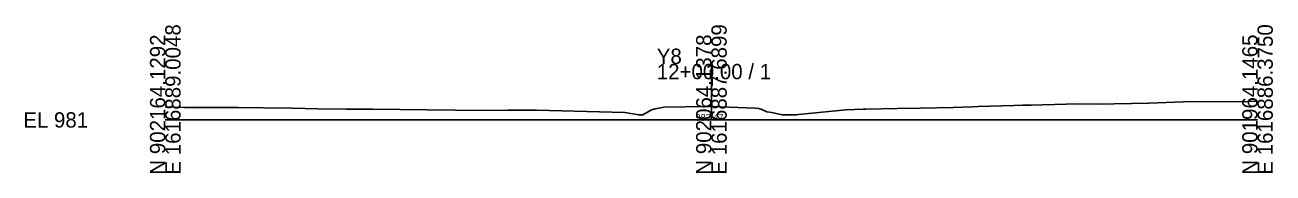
# Model space of a CAD drawing. Extents: x -26 to 1403, y -10 to 3025.
# Drawn here: x -25.7 to 202.8, y 1990.3 to 2017.3 of the extents above; entities that cross this region are included whole.
import ezdxf

# ---------------------------------------------------------------- set-up
doc = ezdxf.new("R2010")
doc.units = 0
for name, color, linetype in [('Exist Cross Section Cell', 7, 'Continuous'), ('Exist XS Center Line Elevation Label', 7, 'Continuous'), ('Exist XS Ground Line', 7, 'Continuous')]:
    doc.layers.add(name, color=color, linetype=linetype)

msp = doc.modelspace()

# ---------------------------------------------------------------- linework, layer by layer
at = {"layer": 'Exist Cross Section Cell'}
for p, q in [((100, 2000), (100, 2010.23)), ((0, 2000), (100, 2000)), ((100, 2000), (200, 2000))]:
    msp.add_line(p, q, dxfattribs=at)
at = {"layer": 'Exist XS Ground Line'}
for p, q in [((0, 2002.38), (3.5, 2002.27)), ((3.5, 2002.27), (7.96, 2002.29)), ((7.96, 2002.29), (13.37, 2002.28)), ((13.37, 2002.28), (17.96, 2002.18)), ((17.96, 2002.18), (23.24, 2002.13)), ((23.24, 2002.13), (27.96, 2002.04)), ((27.96, 2002.04), (33.11, 2001.98)), ((33.11, 2001.98), (37.96, 2001.95)), ((37.96, 2001.95), (42.98, 2001.9)), ((89.04, 2001.87), (89.68, 2002)), ((89.68, 2002), (91.27, 2002.36)), ((91.27, 2002.36), (99.16, 2002.46)), ((99.16, 2002.46), (100.09, 2002.47)), ((100.09, 2002.47), (108.04, 2002.14)), ((108.04, 2002.14), (108.7, 2002.11)), ((108.7, 2002.11), (109.26, 2001.88)), ((127.76, 2001.94), (128.25, 2001.95)), ((128.25, 2001.95), (134.06, 2002.08)), ((134.06, 2002.08), (138.21, 2002.17)), ((138.21, 2002.17), (144.24, 2002.27)), ((144.24, 2002.27), (147.8, 2002.4)), ((147.8, 2002.4), (148.85, 2002.48)), ((148.85, 2002.48), (155.35, 2002.64)), ((155.35, 2002.64), (156.98, 2002.68)), ((156.98, 2002.68), (158.56, 2002.7)), ((158.56, 2002.7), (160.61, 2002.76)), ((160.61, 2002.76), (167.16, 2002.91)), ((167.16, 2002.91), (170.51, 2002.9)), ((170.51, 2002.9), (176.94, 2003.03)), ((176.94, 2003.03), (180.07, 2003.08)), ((180.07, 2003.08), (186.39, 2003.3)), ((186.39, 2003.3), (188.21, 2003.34)), ((188.21, 2003.34), (194.45, 2003.31)), ((194.45, 2003.31), (198.21, 2003.38)), ((198.21, 2003.38), (200, 2003.41)), ((42.98, 2001.9), (47.96, 2001.85)), ((47.96, 2001.85), (53.08, 2001.77)), ((53.08, 2001.77), (57.97, 2001.71)), ((57.97, 2001.71), (62.72, 2001.76)), ((62.72, 2001.76), (67.97, 2001.76)), ((67.97, 2001.76), (81.85, 2001.41)), ((81.85, 2001.41), (84.16, 2001.35)), ((84.16, 2001.35), (86.69, 2000.92)), ((86.69, 2000.92), (87.44, 2000.92)), ((87.44, 2000.92), (89.04, 2001.87)), ((109.26, 2001.88), (110.14, 2001.5)), ((110.14, 2001.5), (111.05, 2001.34)), ((111.05, 2001.34), (112.97, 2000.95)), ((112.97, 2000.95), (113.73, 2000.95)), ((113.73, 2000.95), (115.61, 2000.95)), ((115.61, 2000.95), (115.92, 2000.98)), ((115.92, 2000.98), (124.64, 2001.82)), ((124.64, 2001.82), (127.76, 2001.94))]:
    msp.add_line(p, q, dxfattribs=at)

# ---------------------------------------------------------------- texts
at = {"layer": 'Exist Cross Section Cell'}
for s, p in [('E 1616889.0048', (2.8, 1990)), ('E 1616887.6899', (102.8, 1990)), ('E 1616886.3750', (202.8, 1990)), ('N 902164.1292', (0, 1990)), ('N 902064.1378', (100, 1990)), ('N 901964.1465', (200, 1990))]:
    msp.add_text(s, height=2.8, rotation=90, dxfattribs=at).set_placement(p)
for s, p in [('Y8', (90, 2010.23)), ('12+00.00 / 1', (90, 2007.43)), ('EL 981', (-26, 1998.6))]:
    msp.add_text(s, height=2.8, dxfattribs=at).set_placement(p)
at = {"layer": 'Exist XS Center Line Elevation Label'}
msp.add_text('983.47', height=1.25, dxfattribs=at).set_placement((97.1, 1999.84))

doc.saveas('drawing.dxf')
